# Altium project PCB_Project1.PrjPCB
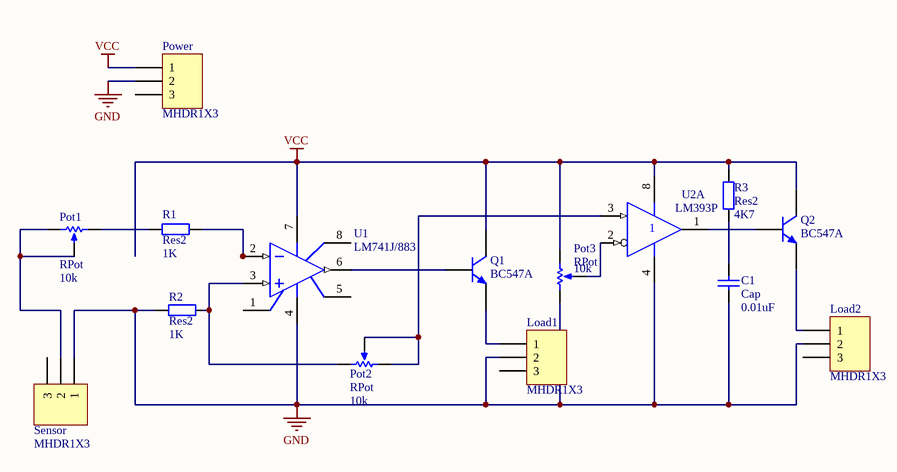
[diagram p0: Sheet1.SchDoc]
1 sheet, 15 parts. Net scope: global (net labels, ports and power ports of the same name join across sheets).
Board file: PCB1.PcbDoc

## Sheet Sheet1.SchDoc
size A4

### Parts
C1  Cap  value 0.01uF  [RAD-0.3]
Load1  MHDR1X3  [MHDR1X3]
Load2  MHDR1X3  [MHDR1X3]
Pot1  RPot  value 10k  [VR5]
Pot2  RPot  value 10k  [VR5]
Pot3  RPot  value 10k  [VR5]
Power  MHDR1X3  [MHDR1X3]
Q1  BC547A  [SOT54]
Q2  BC547A  [SOT54]
R1  Res2  value 1K  [AXIAL-0.4]
R2  Res2  value 1K  [AXIAL-0.4]
R3  Res2  value 4K7  [AXIAL-0.4]
Sensor  MHDR1X3  [MHDR1X3]
U1  LM741J/883  [N08E]
U2  LM393P  [P008]  (part A of 2)

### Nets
GND: C1.1 Load1.2 Load2.2 Pot3.1(TOP) Power.2 R2.1 Sensor.1 U1.4(V-) U2.4(GND)
VCC: Pot3.2(BOT) Power.1 Q1.3(C) Q2.3(C) R3.2 U1.7(V+) U2.8(VCC)
NetC1_2: C1.2 R3.1
NetLoad1_1: Load1.1 Q1.1(E)
NetLoad2_1: Load2.1 Q2.1(E)
NetPot1_1: Pot1.1(TOP) Pot1.3(TAP) Sensor.2
NetPot1_2: Pot1.2(BOT) R1.1
NetPot2_1: Pot2.1(TOP) Pot2.3(TAP) U2.3(IN+)
NetPot2_2: Pot2.2(BOT) R2.2 U1.3(IN+)
NetPot3_3: Pot3.3(TAP) U2.2(IN-)
NetQ1_2: Q1.2(B) U1.6(OUT)
NetQ2_2: Q2.2(B) U2.1(OUT)
NetR1_2: R1.2 U1.2(IN-)

Not connected (* = marked no-connect by the designer): Load1 3; Load2 3; Power 3; Sensor 3; U1 1(OS_NULL) 5(OS_NULL) 8(NC)

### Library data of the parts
C1 = Cap: Capacitor
Load1 Load2 Power Sensor = MHDR1X3: Header, 3-Pin
Pot1-Pot3 = RPot: Potentiometer; Sim Note: Enter the Resistance value and the set point into parameter fields.; Set Position: 0.5
Q1 Q2 = BC547A: NPN General-purpose Transistor
R1-R3 = Res2: Resistor
U1 = LM741J/883: Operational Amplifier
U2 = LM393P: Dual Differential Comparator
